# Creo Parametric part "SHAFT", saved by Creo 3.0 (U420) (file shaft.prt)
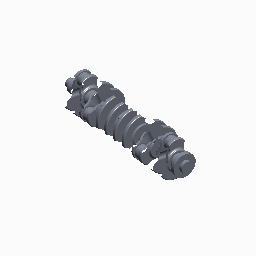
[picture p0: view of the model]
Units: millimeter Kilogram Sec (mmKs); MM, KILOGRAM, SECS

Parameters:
  MATERIAL = "35CrMo"

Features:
  1. datum plane "RIGHT"
  2. datum plane "TOP"
  3. datum plane "FRONT"
  4. coordinate system
  5. curve
  6. protrusion
  7. cut
  8. protrusion
  9. cut
  10. round
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
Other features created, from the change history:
  datum plane "DTM5"
  extrusion "Extrude 8"
  extrusion "Extrude 9"
  extrusion "Extrude 10"
  extrusion "Extrude 11"
  extrusion "Extrude 12"
  extrusion "Extrude 13"
  chamfer "Chamfer 1"
  hole "Hole 1"

Other named items: SHAFT_FROFILE, LOCAL_GROUP, LOCAL_GROUP_1, COPIED_GROUP, LOCAL_GROUP_2, LOCAL_GROUP_3, COPIED_GROUP_1, LOCAL_GROUP_4, LOCAL_GROUP_5, COPIED_GROUP_2, LOCAL_GROUP_6, LOCAL_GROUP_7, COPIED_GROUP_3, LOCAL_GROUP_8, LOCAL_GROUP_9, COPIED_GROUP_4, LOCAL_GROUP_10, LOCAL_GROUP_11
